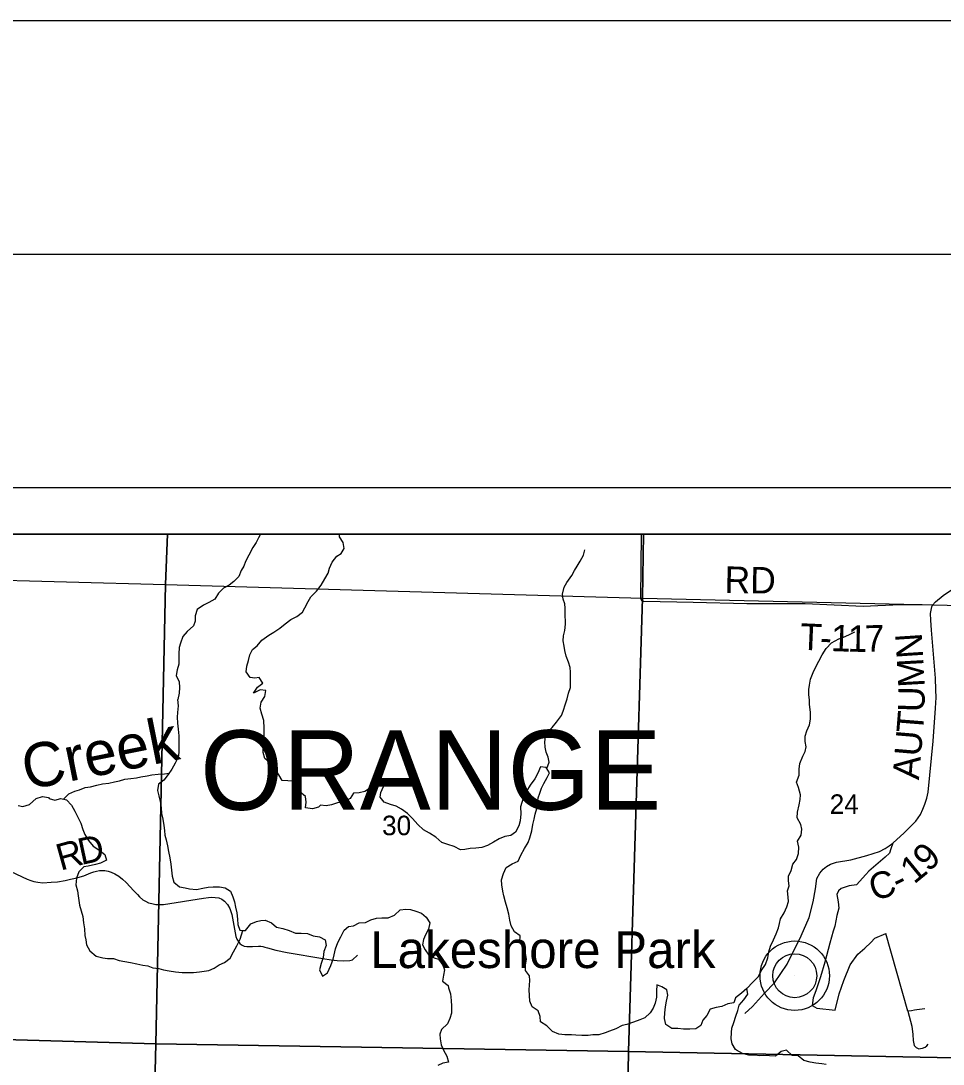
# Model space of a CAD drawing. Extents: x -7.1 to 34, y 0 to 22.
# Drawn here: x 4.434 to 6.409, y 19.764 to 22 of the extents above; entities that cross this region are included whole.
import ezdxf

# ---------------------------------------------------------------- set-up
doc = ezdxf.new("R2010")
doc.units = 0
for name, color, linetype in [('Default', 7, 'Continuous'), ('GM_X_County_Road', 7, 'Continuous'), ('GM_X_County_Road_Text', 7, 'Continuous'), ('GM_X_Major_Lake', 7, 'Continuous'), ('GM_X_Major_River', 7, 'Continuous'), ('GM_X_Major_River_Text', 7, 'Continuous'), ('GM_X_Minor_River', 7, 'Continuous'), ('GM_X_Section', 7, 'Continuous'), ('GM_X_Section_Text', 7, 'Continuous'), ('GM_X_Township_Road', 7, 'Continuous'), ('GM_X_Township_Road_Text', 7, 'Continuous'), ('GM_X_Township_Text', 7, 'Continuous'), ('GM_X_Unincorporated', 7, 'Continuous'), ('GM_X_Unincorporated_Location', 7, 'Continuous'), ('GM_X_Unincorporated_Text', 7, 'Continuous'), ('SH_Border', 7, 'Continuous'), ('SH_Cut_Line', 7, 'Continuous'), ('SH_Data', 7, 'Continuous')]:
    doc.layers.add(name, color=color, linetype=linetype)

msp = doc.modelspace()

# ---------------------------------------------------------------- linework, layer by layer
at = {"layer": 'Default'}
for points in [[(4.7475, 20.9), (3.8966, 20.9), (3.8945, 20.8149), (4.7431, 20.792)], [(5.7672, 20.9), (4.7475, 20.9), (4.7431, 20.792), (5.765, 20.7626)], [(6.7945, 20.9), (5.7672, 20.9), (5.765, 20.7626), (6.791, 20.7388)]]:
    msp.add_lwpolyline(points, close=True, dxfattribs=at)
at = {"layer": 'GM_X_County_Road'}
msp.add_lwpolyline([(5.9843, 19.8722), (6.0004, 19.8873), (6.0266, 19.9159), (6.0476, 19.9384), (6.0748, 19.978), (6.105, 20.0391), (6.1223, 20.0779), (6.131, 20.1114), (6.1359, 20.1395), (6.1387, 20.1617), (6.1448, 20.1729), (6.1521, 20.1819), (6.159, 20.1876), (6.168, 20.1923), (6.1806, 20.1964), (6.2116, 20.2019), (6.2459, 20.2108), (6.2727, 20.2197), (6.2851, 20.2261), (6.2932, 20.2318), (6.3016, 20.2376), (6.3257, 20.2599), (6.3505, 20.2845), (6.3606, 20.2989), (6.3656, 20.3103), (6.37, 20.3209), (6.374, 20.3336), (6.377, 20.3465), (6.388, 20.4564), (6.3924, 20.5265), (6.394, 20.5497), (6.3935, 20.566), (6.393, 20.591), (6.3843, 20.694), (6.3825, 20.7151), (6.3823, 20.7301), (6.3835, 20.7367), (6.3848, 20.7439), (6.386, 20.7477), (6.3928, 20.7551), (6.4089, 20.768), (6.4292, 20.7821)], dxfattribs=at)
at = {"layer": 'GM_X_Major_Lake'}
for points in [[(4.9467, 20.9), (4.9429, 20.8916), (4.9377, 20.8817), (4.9307, 20.8709), (4.9215, 20.8549), (4.9145, 20.8411), (4.9108, 20.8312), (4.9057, 20.8216), (4.9002, 20.8094), (4.8897, 20.7986), (4.88, 20.7908), (4.8679, 20.7838), (4.8571, 20.773), (4.8493, 20.7604), (4.8365, 20.7533), (4.8248, 20.7474), (4.8109, 20.7381), (4.8069, 20.7251), (4.8068, 20.713), (4.8031, 20.7035), (4.79, 20.6915), (4.7803, 20.6803), (4.7756, 20.6662), (4.7727, 20.6567), (4.7718, 20.6434), (4.7716, 20.6339), (4.7718, 20.6214), (4.7686, 20.6092), (4.7665, 20.597), (4.7728, 20.5831), (4.7734, 20.571), (4.7725, 20.5588), (4.7696, 20.5455)], [(4.9298, 20.6528), (4.9395, 20.6606), (4.95, 20.6725), (4.965, 20.683), (4.9752, 20.6896), (4.988, 20.6981), (5, 20.7078), (5.012, 20.7167), (5.0244, 20.7234), (5.0368, 20.7323), (5.0416, 20.7419), (5.0486, 20.7553), (5.0549, 20.7652), (5.0665, 20.7776), (5.0765, 20.7903), (5.0846, 20.8037), (5.092, 20.8159), (5.0949, 20.8266), (5.1004, 20.8396), (5.1101, 20.8523), (5.1198, 20.8585), (5.1261, 20.8692), (5.124, 20.8821), (5.1162, 20.8941), (5.1157, 20.9)], [(5.0712, 20.3148), (5.0583, 20.3112), (5.0434, 20.3129), (5.0444, 20.3254), (5.043, 20.3375), (5.0311, 20.3472), (5.0248, 20.3588), (5.017, 20.3701), (5.0056, 20.3711), (4.9934, 20.372), (4.9864, 20.3836), (4.9782, 20.396), (4.9685, 20.4088), (4.9561, 20.4188), (4.9525, 20.4316), (4.9523, 20.4453), (4.9532, 20.4571), (4.9545, 20.47), (4.955, 20.484), (4.954, 20.5007), (4.9496, 20.5143), (4.946, 20.5267), (4.948, 20.5397), (4.9558, 20.5519), (4.9579, 20.5645), (4.9464, 20.5658), (4.9321, 20.5591), (4.9403, 20.5722), (4.9515, 20.5807), (4.9441, 20.5923), (4.9346, 20.5914), (4.9247, 20.5928), (4.9162, 20.6044), (4.9178, 20.6166), (4.9211, 20.6288), (4.9243, 20.6413), (4.9298, 20.6528)], [(4.7696, 20.5455), (4.7693, 20.5455), (4.7703, 20.5318), (4.769, 20.5178), (4.7684, 20.5075), (4.769, 20.4946), (4.7703, 20.4818), (4.7717, 20.4677), (4.7719, 20.4548), (4.7718, 20.4419), (4.7719, 20.4321), (4.7702, 20.4218), (4.7643, 20.4088), (4.7566, 20.3962), (4.7491, 20.3847), (4.7395, 20.3728), (4.7286, 20.3638), (4.7261, 20.3505), (4.729, 20.3392), (4.7319, 20.3267), (4.7344, 20.3142), (4.735, 20.3014), (4.7378, 20.2889), (4.7396, 20.2756), (4.7409, 20.2643), (4.7422, 20.2544), (4.745, 20.2446), (4.7475, 20.2318), (4.75, 20.2193), (4.7525, 20.2057), (4.7546, 20.1924), (4.7564, 20.1796), (4.7573, 20.167), (4.7614, 20.1542), (4.7733, 20.1442), (4.7855, 20.1417), (4.7951, 20.1396), (4.8099, 20.1379), (4.8232, 20.1412), (4.8349, 20.1429), (4.8452, 20.1442), (4.8588, 20.1437), (4.8714, 20.1416), (4.8826, 20.1346), (4.8873, 20.1225), (4.8909, 20.112), (4.893, 20.1002), (4.8959, 20.0881), (4.8976, 20.0749), (4.8982, 20.0631), (4.9026, 20.0507), (4.909, 20.0504)], [(5.5599, 19.8457), (5.5464, 19.8542), (5.5458, 19.8659), (5.5415, 19.878), (5.5288, 19.8865), (5.524, 19.8989), (5.5227, 19.9107), (5.5225, 19.9228), (5.5227, 19.9334), (5.5237, 19.9429), (5.5227, 19.9528), (5.5146, 19.9644), (5.5147, 19.9762), (5.5164, 19.9887), (5.5147, 20.0016), (5.5092, 20.0129), (5.5025, 20.026), (5.5031, 20.0386), (5.4911, 20.0475), (5.4837, 20.0606), (5.4808, 20.0727), (5.4791, 20.0856), (5.4754, 20.0988), (5.4714, 20.1113), (5.4682, 20.1249), (5.4661, 20.1347), (5.4636, 20.1483), (5.4634, 20.1589), (5.4677, 20.1727), (5.4729, 20.1853), (5.4856, 20.1931), (5.4989, 20.1986), (5.5047, 20.2116), (5.5121, 20.2257), (5.5202, 20.2388), (5.5239, 20.2487), (5.5278, 20.2639), (5.5302, 20.2776), (5.5327, 20.2887), (5.5352, 20.2993), (5.5388, 20.3119), (5.5405, 20.3214), (5.5418, 20.3347), (5.5451, 20.345), (5.5491, 20.3557), (5.5539, 20.3657), (5.5609, 20.3783), (5.566, 20.3879), (5.559, 20.3999), (5.5464, 20.4008), (5.5406, 20.3874), (5.5343, 20.3752), (5.5246, 20.3618), (5.5169, 20.3491), (5.511, 20.3369), (5.5063, 20.325), (5.5041, 20.3151), (5.5044, 20.3), (5.5027, 20.2851), (5.4999, 20.2749), (5.4933, 20.2611), (5.4831, 20.2537), (5.4702, 20.2516), (5.4581, 20.2469), (5.4461, 20.2398), (5.4329, 20.2324), (5.4208, 20.2284), (5.4079, 20.2267), (5.3958, 20.2257), (5.3844, 20.224), (5.3749, 20.2235), (5.3619, 20.2305), (5.3481, 20.2344), (5.3355, 20.2391), (5.3227, 20.2503), (5.3089, 20.2588), (5.2963, 20.2662), (5.2835, 20.2777), (5.2727, 20.2901), (5.2618, 20.3013), (5.2491, 20.3106), (5.2376, 20.3168), (5.225, 20.3204), (5.212, 20.3255), (5.2031, 20.3364), (5.2044, 20.3459), (5.2103, 20.3589), (5.2177, 20.3719), (5.2078, 20.3755), (5.1942, 20.3669), (5.1845, 20.3577), (5.1706, 20.3483), (5.1581, 20.3455), (5.1463, 20.3445), (5.1389, 20.333), (5.1261, 20.3267), (5.1121, 20.3239), (5.0992, 20.3199), (5.0878, 20.3178), (5.0756, 20.3191), (5.0712, 20.3148)], [(4.909, 20.0504), (4.9148, 20.0501), (4.9263, 20.0647), (4.938, 20.0699), (4.9475, 20.0715), (4.957, 20.0725), (4.9704, 20.067), (4.9812, 20.0573), (4.9949, 20.0545), (5.0083, 20.0505), (5.0217, 20.0447), (5.0342, 20.0449), (5.0475, 20.044), (5.0598, 20.0385), (5.0735, 20.0364), (5.0854, 20.0302), (5.0875, 20.0181), (5.0828, 20.0051), (5.0811, 19.9925), (5.0771, 19.9796), (5.0732, 19.9659), (5.0795, 19.9527), (5.09, 19.9593), (5.0977, 19.9754), (5.1028, 19.9887), (5.1046, 19.9982), (5.1074, 20.0108), (5.1125, 20.0246), (5.1191, 20.0368), (5.1257, 20.0513), (5.1355, 20.0591), (5.1457, 20.0604), (5.1582, 20.067), (5.1715, 20.0673), (5.1831, 20.0731), (5.1953, 20.0767), (5.207, 20.0773), (5.22, 20.0772), (5.2339, 20.0835), (5.2463, 20.0947), (5.2584, 20.096), (5.2679, 20.095), (5.2798, 20.0914), (5.2916, 20.0871), (5.3017, 20.0789), (5.3095, 20.0665), (5.3066, 20.0535), (5.3004, 20.0409), (5.296, 20.031), (5.2935, 20.0196), (5.2994, 20.009)], [(5.2994, 20.009), (5.3076, 19.9974), (5.3187, 19.9915), (5.3283, 19.9886), (5.3372, 19.9759), (5.3408, 19.9661), (5.3387, 19.9547), (5.337, 19.9414), (5.349, 19.9325)], [(5.349, 19.9325), (5.3498, 19.9275), (5.3538, 19.9147), (5.3556, 19.9003), (5.3562, 19.8878), (5.356, 19.8734), (5.3524, 19.8616), (5.3473, 19.8501), (5.3349, 19.8381), (5.3313, 19.8278), (5.3319, 19.8184), (5.3336, 19.8055), (5.3387, 19.7938), (5.3458, 19.781), (5.3498, 19.7682), (5.3377, 19.7661), (5.3267, 19.761)], [(5.9641, 19.7951), (5.9574, 19.8071), (5.9553, 19.8181), (5.9555, 19.8317), (5.9564, 19.8412), (5.9604, 19.8534), (5.9648, 19.8664), (5.9691, 19.879), (5.9723, 19.8904), (5.982, 19.9016), (5.9906, 19.9135), (5.9889, 19.926), (5.9772, 19.9159), (5.9641, 19.9062), (5.9605, 19.8952), (5.9476, 19.8934), (5.9348, 19.8875), (5.9226, 19.8854), (5.9101, 19.8818), (5.9028, 19.868), (5.8946, 19.8584), (5.8902, 19.847), (5.8793, 19.8392), (5.8668, 19.8386), (5.8527, 19.8391), (5.8409, 19.8405), (5.828, 19.8402), (5.8153, 19.8491), (5.8124, 19.8616), (5.813, 19.8738), (5.8146, 19.8867), (5.8167, 19.8989), (5.8196, 19.9118), (5.8175, 19.9231), (5.8063, 19.9294), (5.7956, 19.9338), (5.7951, 19.9205), (5.7953, 19.9076), (5.7921, 19.8947), (5.7877, 19.884), (5.7818, 19.874), (5.7702, 19.8632), (5.7592, 19.8588), (5.7456, 19.8537), (5.7316, 19.8489), (5.7218, 19.8464), (5.7078, 19.8398), (5.6946, 19.8342), (5.6848, 19.8307), (5.6719, 19.827), (5.6586, 19.8264), (5.6488, 19.8251), (5.6351, 19.8249), (5.6225, 19.8258), (5.613, 19.8264), (5.5986, 19.8266), (5.5856, 19.8283), (5.5722, 19.8337), (5.5599, 19.8457)], [(6.1588, 19.7634), (6.1493, 19.7644), (6.1367, 19.7661), (6.1245, 19.7682), (6.1108, 19.7717), (6.0989, 19.7814), (6.0859, 19.7827), (6.0739, 19.7939), (6.0622, 19.7906), (6.0502, 19.781), (6.0373, 19.7815), (6.0251, 19.7821), (6.0156, 19.7819), (6.0061, 19.7829), (5.9928, 19.783), (5.9794, 19.7866), (5.9667, 19.794), (5.9641, 19.7951)]]:
    msp.add_lwpolyline(points, dxfattribs=at)
at = {"layer": 'GM_X_Major_River'}
for points in [[(4.4279, 20.3179), (4.4374, 20.3162), (4.4518, 20.3202), (4.466, 20.3333), (4.4797, 20.3374), (4.493, 20.3353)], [(4.493, 20.3353), (4.4938, 20.3334), (4.5064, 20.3295), (4.5193, 20.3331), (4.5315, 20.3303), (4.5423, 20.3187), (4.549, 20.3063), (4.5557, 20.2931), (4.562, 20.2803), (4.5664, 20.2671), (4.5707, 20.2558), (4.5785, 20.243), (4.5886, 20.2307), (4.6002, 20.2229), (4.6133, 20.2129), (4.6169, 20.2012), (4.6044, 20.1945), (4.5935, 20.192), (4.5779, 20.1884), (4.5681, 20.1871), (4.5576, 20.1759), (4.5529, 20.1622), (4.5516, 20.1485), (4.5549, 20.1353), (4.5566, 20.1247), (4.5579, 20.1148), (4.5592, 20.1046), (4.5624, 20.0921), (4.5661, 20.0801), (4.5678, 20.0664), (4.5695, 20.0539), (4.5709, 20.0399), (4.5726, 20.0301), (4.5739, 20.0199), (4.581, 20.0067), (4.5949, 19.9952), (4.609, 19.9916), (4.6193, 19.9903), (4.6322, 19.9901), (4.644, 19.9861), (4.6562, 19.9837), (4.6681, 19.9816), (4.6818, 19.9788), (4.6948, 19.9759), (4.7054, 19.9742), (4.7165, 19.9706), (4.7291, 19.9685), (4.7394, 19.9661), (4.7512, 19.9636), (4.7646, 19.9619), (4.7787, 19.9603), (4.7916, 19.9601), (4.8034, 19.9603), (4.8163, 19.9616), (4.8261, 19.9629), (4.836, 19.9646), (4.8477, 19.9697), (4.8582, 19.9764), (4.8695, 19.9819), (4.8815, 19.9912), (4.8893, 20.0046), (4.8959, 20.0172), (4.9033, 20.0317), (4.9062, 20.0413), (4.909, 20.0504)]]:
    msp.add_lwpolyline(points, dxfattribs=at)
at = {"layer": 'GM_X_Minor_River'}
for points in [[(5.5603, 20.3976), (5.5649, 20.4108), (5.5633, 20.4218), (5.5587, 20.4328), (5.5567, 20.443), (5.5558, 20.4544), (5.5576, 20.4654), (5.561, 20.4757), (5.5715, 20.4852), (5.5809, 20.4967), (5.5918, 20.5108), (5.5955, 20.5207), (5.6003, 20.5363), (5.6036, 20.547), (5.6069, 20.5587), (5.6106, 20.5713), (5.6109, 20.5808), (5.6107, 20.6039), (5.6099, 20.6142), (5.6064, 20.6255), (5.6017, 20.6384), (5.5985, 20.6501), (5.5973, 20.6596), (5.5949, 20.6713), (5.5956, 20.6819), (5.5985, 20.6933), (5.5999, 20.7066), (5.5997, 20.7309), (5.5993, 20.7411), (5.5984, 20.7506), (5.5953, 20.7608), (5.5937, 20.7714), (5.5973, 20.7863), (5.603, 20.7962), (5.6135, 20.8111), (5.6191, 20.8217), (5.6254, 20.8313), (5.6318, 20.8416), (5.6385, 20.8549), (5.6415, 20.8659)], [(5.9889, 19.926), (6.0014, 19.9392), (6.0134, 19.9518), (6.0194, 19.9636), (6.0288, 19.9774), (6.0336, 19.9914), (6.0357, 20.0044), (6.0391, 20.0169), (6.0458, 20.0302), (6.0517, 20.0428), (6.0566, 20.0558), (6.0584, 20.0653), (6.061, 20.0751), (6.0684, 20.0881), (6.074, 20.1007), (6.0781, 20.1121), (6.0769, 20.1219), (6.076, 20.1356), (6.0793, 20.1462), (6.0781, 20.1565), (6.0776, 20.1671), (6.0836, 20.1789), (6.0873, 20.1922), (6.0948, 20.2025), (6.0992, 20.2155), (6.0999, 20.2287), (6.0971, 20.2416), (6.1053, 20.2546), (6.1067, 20.2675), (6.1044, 20.2773), (6.0967, 20.2921), (6.0969, 20.3042), (6.1006, 20.3198), (6.1031, 20.3312), (6.1034, 20.3414), (6.0991, 20.3566), (6.0948, 20.3679), (6.1004, 20.3831), (6.101, 20.3964), (6.1021, 20.4082), (6.1088, 20.4238), (6.1133, 20.4337), (6.1158, 20.444), (6.1138, 20.4557), (6.1133, 20.4667), (6.1174, 20.4785), (6.123, 20.4914), (6.1248, 20.5036), (6.1251, 20.5173), (6.123, 20.5351), (6.1229, 20.5449), (6.1217, 20.5552), (6.1216, 20.5665), (6.1226, 20.576), (6.1252, 20.589), (6.1308, 20.603), (6.1367, 20.6152), (6.1427, 20.6278), (6.1502, 20.6415), (6.1588, 20.6545), (6.1701, 20.6667), (6.1856, 20.6756), (6.1992, 20.6806), (6.2098, 20.6853), (6.2196, 20.6903)], [(4.5249, 20.3318), (4.5365, 20.3434), (4.549, 20.3488), (4.5589, 20.3519), (4.5714, 20.3566), (4.5824, 20.3582), (4.596, 20.3621), (4.6081, 20.3645), (4.6222, 20.3661), (4.6343, 20.3689), (4.6449, 20.3709), (4.6563, 20.3744), (4.6688, 20.3764), (4.6809, 20.3772), (4.6908, 20.38), (4.7041, 20.382), (4.7143, 20.384), (4.7276, 20.3852), (4.7413, 20.3861), (4.7509, 20.3875)]]:
    msp.add_lwpolyline(points, dxfattribs=at)
at = {"layer": 'GM_X_Section'}
for points in [[(3.8945, 20.8149), (4.7431, 20.792), (4.7229, 19.8074), (3.8731, 19.8315), (3.8931, 20.7247)], [(4.7431, 20.792), (5.765, 20.7626), (5.7351, 19.7911), (4.7229, 19.8074)], [(5.765, 20.7626), (6.791, 20.7388), (6.7637, 19.7708), (5.7351, 19.7911)], [(3.8731, 19.8315), (4.7229, 19.8074), (4.6987, 18.8125), (3.8597, 18.828), (3.8749, 19.7341)], [(4.7229, 19.8074), (5.7351, 19.7911), (5.7181, 18.7951), (4.6987, 18.8125)], [(6.7637, 19.7708), (6.7487, 18.7741), (5.7181, 18.7951), (5.7351, 19.7911)]]:
    msp.add_lwpolyline(points, close=True, dxfattribs=at)
at = {"layer": 'GM_X_Township_Road'}
for points in [[(3.0659, 17.6986), (3.7215, 17.6707), (3.8238, 17.6717), (3.8304, 17.7952), (4.3, 17.7873), (4.5657, 17.7857), (4.7094, 17.7848), (5.0443, 17.7832), (5.0544, 17.7831), (5.1115, 17.7819), (5.5047, 17.7737), (5.7514, 17.7685), (6.1904, 17.7592), (6.3575, 17.7557), (6.7118, 17.7486), (6.7254, 18.1319), (6.7433, 18.7732), (6.7479, 19.0295), (6.7613, 19.7723), (6.7882, 20.743), (6.7921, 20.9), (2.1, 20.9)], [(6.386, 20.7477), (6.3639, 20.7486), (6.3167, 20.7486), (6.2376, 20.7445), (6.1133, 20.7503), (5.9886, 20.7507), (5.8738, 20.7531), (5.7679, 20.7552), (5.7663, 20.7558), (5.7645, 20.7571), (5.7625, 20.7594), (5.7617, 20.7616), (5.7627, 20.9)], [(6.3016, 20.2376), (6.2971, 20.2253), (6.2945, 20.216), (6.2852, 20.2077), (6.2499, 20.1773), (6.2437, 20.1706)], [(4.4122, 20.1768), (4.447, 20.1604), (4.4547, 20.1575), (4.4615, 20.1553), (4.4702, 20.1536), (4.4803, 20.1525), (4.4987, 20.1536), (4.5122, 20.1549), (4.5283, 20.1578), (4.5401, 20.16), (4.5508, 20.1624), (4.5681, 20.1677), (4.5834, 20.174), (4.5897, 20.176), (4.5953, 20.1777), (4.6017, 20.1789), (4.6078, 20.1791), (4.6136, 20.179), (4.6207, 20.1775), (4.6272, 20.1753), (4.6345, 20.1719), (4.6431, 20.1666), (4.6515, 20.1601), (4.6588, 20.1532), (4.6758, 20.1351), (4.6833, 20.1271), (4.6876, 20.1224), (4.6946, 20.1161), (4.7005, 20.1129), (4.7071, 20.1099), (4.7138, 20.1079), (4.7227, 20.1063), (4.7389, 20.106), (4.8249, 20.1196), (4.8356, 20.121), (4.8429, 20.1218), (4.8496, 20.1213), (4.8575, 20.12), (4.8639, 20.1172), (4.8699, 20.1129), (4.8762, 20.1062), (4.8813, 20.0973), (4.8855, 20.0843), (4.8939, 20.0376), (4.8962, 20.0318), (4.8987, 20.0272), (4.9024, 20.0226), (4.9064, 20.0196), (4.9121, 20.017), (4.9175, 20.0161), (4.9299, 20.0159), (4.9428, 20.0166), (4.9474, 20.0166), (4.9516, 20.016), (4.9561, 20.0148), (4.9617, 20.0131), (4.9795, 20.0082), (5.0036, 20.0028), (5.0807, 19.9905), (5.0984, 19.9873), (5.1111, 19.9861), (5.1249, 19.9851), (5.1379, 19.9859), (5.1438, 19.9873), (5.1548, 19.9975)], [(6.2437, 20.1706), (6.2233, 20.1484), (6.2078, 20.1458), (6.1907, 20.1402), (6.1851, 20.1352), (6.1812, 20.1277), (6.1842, 20.1116), (6.1855, 20.0981), (6.1815, 20.0826), (6.1769, 20.0599), (6.1736, 20.0486)], [(6.1736, 20.0486), (6.1661, 20.0231), (6.1559, 19.9827), (6.1463, 19.9508), (6.1365, 19.9209), (6.1309, 19.9057), (6.1286, 19.8893), (6.1388, 19.8837), (6.1776, 19.8798)], [(6.1776, 19.8798), (6.1865, 19.9143), (6.1963, 19.9432), (6.2098, 19.9768), (6.2266, 19.9998), (6.241, 20.0126), (6.2545, 20.0244), (6.2631, 20.034), (6.2861, 20.0442)], [(6.3696, 19.8821), (6.3525, 19.8801), (6.3476, 19.8794), (6.3413, 19.8784), (6.3334, 19.8775), (6.2861, 20.0442)], [(6.3334, 19.8775), (6.3417, 19.8452), (6.344, 19.8275), (6.3451, 19.8145), (6.3461, 19.8076), (6.3471, 19.804), (6.3514, 19.7997), (6.357, 19.7967), (6.3604, 19.7977), (6.3652, 19.7982), (6.3704, 19.8002), (6.3744, 19.8033), (6.377, 19.8064)]]:
    msp.add_lwpolyline(points, dxfattribs=at)
at = {"layer": 'GM_X_Unincorporated'}
for radius in [0.0744, 0.0472]:
    msp.add_circle((6.0912, 19.9534), radius, dxfattribs=at)
at = {"layer": 'GM_X_Unincorporated_Location'}
msp.add_line((6.0912, 19.9534), (6.0912, 19.9534), dxfattribs=at)
at = {"layer": 'SH_Border'}
msp.add_lwpolyline([(1.5, 21.5), (33.5, 21.5), (33.5, 0.5), (1.5, 0.5)], close=True, dxfattribs=at)
at = {"layer": 'SH_Cut_Line'}
for points in [[(0, 0), (34, 0), (34, 22), (0, 22)], [(8.9, 17.7079), (8.9, 20.9), (2.1, 20.9), (2.1, 17.7253), (2.5551, 17.7155), (2.7886, 17.7105), (3.0659, 17.6986), (3.7215, 17.6707), (3.8238, 17.6717), (3.8304, 17.7952), (4.3, 17.7873), (4.5657, 17.7857), (4.7094, 17.7848), (5.0443, 17.7832), (5.0544, 17.7831), (5.1115, 17.7819), (5.5047, 17.7737), (5.7514, 17.7685), (6.1904, 17.7592), (6.3575, 17.7557), (6.7118, 17.7486), (7.7202, 17.7285), (8.4472, 17.7189), (8.6668, 17.7136)]]:
    msp.add_lwpolyline(points, close=True, dxfattribs=at)
at = {"layer": 'SH_Data'}
for p, q in [((2, 21), (9, 21)), ((2.1, 20.9), (8.9, 20.9))]:
    msp.add_line(p, q, dxfattribs=at)

# ---------------------------------------------------------------- texts
at = {"layer": 'GM_X_County_Road_Text'}
for s, rotation, p in [('N', 93.7532, (6.3665, 20.635)), ('M', 93.2844, (6.37, 20.5729)), ('U', 88.7388, (6.369, 20.518)), ('T', 85.4755, (6.3655, 20.4721)), ('U', 85.2261, (6.3613, 20.422)), ('A', 85.2297, (6.3572, 20.3722)), ('9', 44.1561, (6.3778, 20.1739)), ('1', 39.3224, (6.3468, 20.1483)), ('C', 17.687, (6.2609, 20.1127)), ('-', 26.0766, (6.3138, 20.1303))]:
    msp.add_text(s, height=0.0568, rotation=rotation, dxfattribs=at).set_placement(p)
at = {"layer": 'GM_X_Major_River_Text'}
msp.add_text('Creek', height=0.0947, rotation=11.4091, dxfattribs=at).set_placement((4.4463, 20.351))
at = {"layer": 'GM_X_Section_Text'}
for s, p in [('24', (6.1661, 20.3002)), ('30', (5.2073, 20.2545))]:
    msp.add_text(s, height=0.04186, rotation=0, dxfattribs=at).set_placement(p)
at = {"layer": 'GM_X_Township_Road_Text'}
for s, height, rotation, p in [('RD', 0.05682, 359.0293, (5.9404, 20.774)), ('T', 0.0568, 357.4727, (6.1017, 20.6522)), ('1', 0.0568, 357.9312, (6.168, 20.6493)), ('1', 0.0568, 358.9515, (6.2041, 20.648)), ('7', 0.0568, 1.7317, (6.2421, 20.6474)), ('-', 0.0568, 357.5755, (6.1443, 20.6503)), ('R', 0.0568, 15.4961, (4.5185, 20.1782)), ('D', 0.0568, 12.208, (4.5626, 20.1905))]:
    msp.add_text(s, height=height, rotation=rotation, dxfattribs=at).set_placement(p)
at = {"layer": 'GM_X_Township_Text'}
msp.add_text('ORANGE', height=0.17045, rotation=0, dxfattribs=at).set_placement((4.8177, 20.309))
at = {"layer": 'GM_X_Unincorporated_Text'}
msp.add_text('Lakeshore Park', height=0.078977, rotation=0, dxfattribs=at).set_placement((5.1819, 19.9698))

doc.saveas('drawing.dxf')
